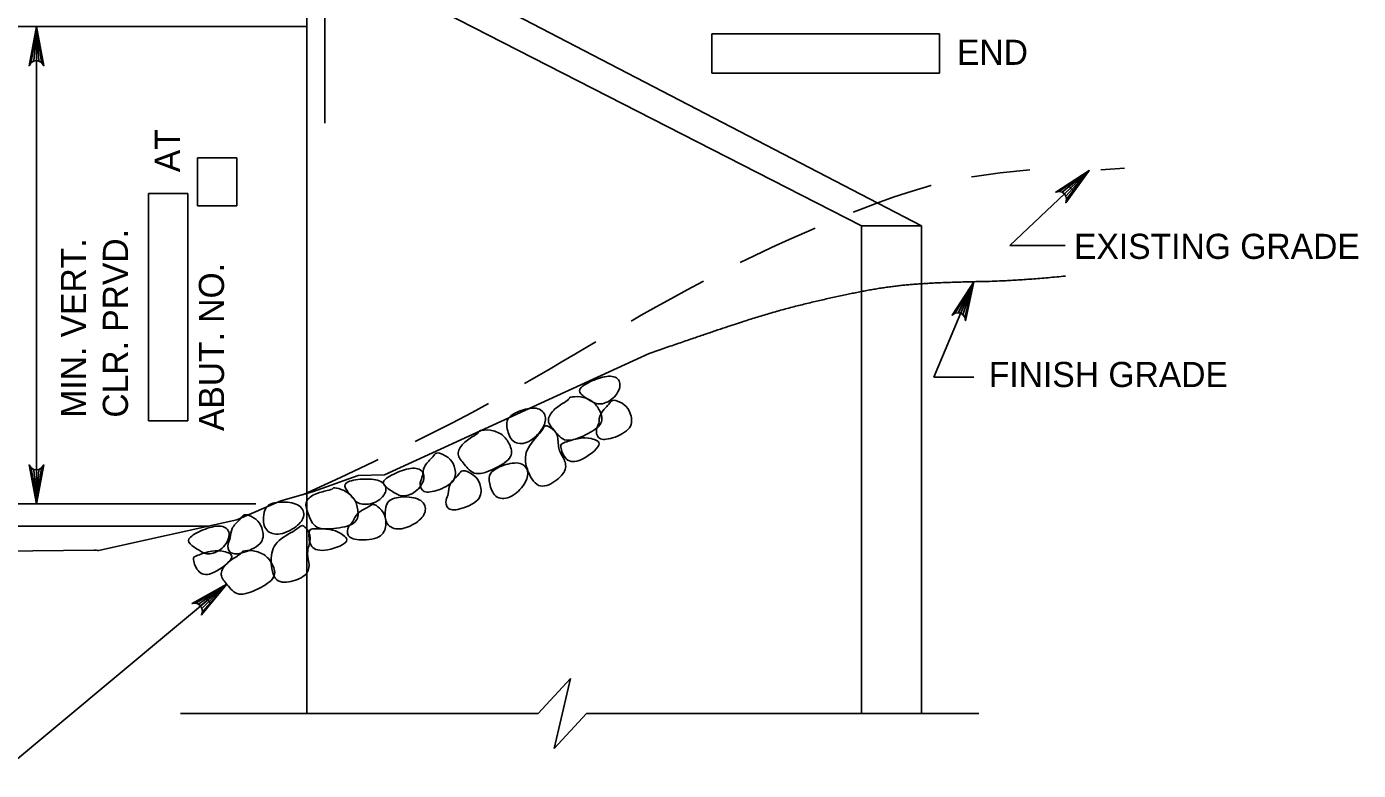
# Model space of a CAD drawing. Extents: x 638268 to 640277, y 295465 to 298435.
# Drawn here: x 638715.2 to 638874.1, y 296757 to 296845.8 of the extents above; entities that cross this region are included whole.
import ezdxf

# ---------------------------------------------------------------- set-up
doc = ezdxf.new("R2010")
doc.units = 0
for name, color, linetype in [('3', 7, 'Continuous'), ('4', 7, 'Continuous'), ('8', 7, 'Continuous')]:
    doc.layers.add(name, color=color, linetype=linetype)

msp = doc.modelspace()

# ---------------------------------------------------------------- linework, layer by layer
at = {"layer": '3'}
for p, q in [((638748.57, 296855.85), (638814.78, 296821.97)), ((638756.79, 296855.85), (638821.91, 296821.97)), ((638748.57, 296851.52), (638748.57, 296790.02)), ((638569.79, 296845.75), (638748.57, 296845.75)), ((638569.79, 296845.75), (638748.57, 296845.75)), ((638841.94, 296828.56), (638832.45, 296819.63)), ((638814.78, 296821.97), (638821.91, 296821.97)), ((638814.78, 296814.12), (638814.78, 296821.97)), ((638821.91, 296821.97), (638821.91, 296815.02)), ((638832.45, 296819.63), (638839.05, 296819.63)), ((638821.91, 296815.02), (638821.91, 296763.74)), ((638828.17, 296815.28), (638823.41, 296803.89)), ((638814.78, 296763.74), (638814.78, 296814.12)), ((638789.43, 296806.73), (638757.84, 296792.24)), ((638823.41, 296803.89), (638828.18, 296803.89)), ((638757.84, 296792.24), (638754.69, 296792.17)), ((638748.57, 296790.02), (638748.57, 296763.74)), ((638576.14, 296786.13), (638736.87, 296786.13)), ((638776.18, 296763.74), (638780.03, 296767.92)), ((638780.03, 296767.92), (638778.1, 296759.57)), ((638733.5, 296763.74), (638776.18, 296763.74)), ((638778.1, 296759.57), (638781.95, 296763.74)), ((638781.95, 296763.74), (638828.77, 296763.74))]:
    msp.add_line(p, q, dxfattribs=at)
for points in [[(638839.39, 296826.84), (638840.06, 296826.12), (638841.88, 296828.51)], [(638826.58, 296812.74), (638827.49, 296812.37), (638828.17, 296815.28)]]:
    msp.add_lwpolyline(points, close=True, dxfattribs=at)
msp.add_lwpolyline([(638634.43, 296782.51), (638657.14, 296782.51), (638723.2, 296783.23)], dxfattribs=at)
msp.add_arc((638723.2, 296771.75), 11.48, 87.4213, 90, dxfattribs=at)
for points, degree in [([(638789.43, 296806.73), (638797.21, 296809.42), (638804.35, 296811.74), (638811.5, 296813.49), (638818.25, 296814.8), (638824.6, 296815.24), (638833.14, 296815.38), (638839.1, 296815.97)], 2), ([(638781.29, 296801.9), (638781.53, 296801.64), (638782.4, 296801.09), (638783.51, 296800.44), (638785.49, 296801.38), (638786.25, 296803.31), (638785.16, 296804.22), (638783.14, 296803.78), (638780.96, 296802.63), (638781.05, 296802.16), (638781.29, 296801.9)], 3), ([(638779.88, 296801.34), (638779.83, 296801.26), (638779.49, 296800.97), (638777.91, 296800.05), (638777.11, 296798.62), (638778.12, 296797.57), (638779.32, 296795.94), (638781.9, 296796.94), (638784.12, 296798.36), (638783.57, 296799.95), (638782.78, 296801.08), (638781.18, 296801.69), (638779.83, 296801.48), (638779.94, 296801.43), (638779.88, 296801.34)], 3), ([(638783.41, 296798.4), (638783.35, 296798.1), (638783.05, 296797.73), (638783.2, 296796.51), (638784.54, 296796.34), (638787.44, 296797.59), (638787.34, 296799.35), (638786.83, 296800.45), (638785.57, 296801.15), (638784.91, 296801.18), (638784.62, 296800.57), (638783.44, 296799.54), (638783.48, 296798.7), (638783.41, 296798.4)], 3), ([(638772.65, 296799), (638772.37, 296798.63), (638772.41, 296797.79), (638773.04, 296795.97), (638774.88, 296795.83), (638776.63, 296797.45), (638777.33, 296799.09), (638776.36, 296800.43), (638774.09, 296800.02), (638772.93, 296799.37), (638772.65, 296799)], 3), ([(638769.11, 296797.36), (638769.05, 296797.28), (638768.72, 296796.99), (638767.13, 296796.07), (638766.34, 296794.64), (638767.34, 296793.59), (638768.54, 296791.96), (638771.12, 296792.96), (638773.34, 296794.38), (638772.79, 296795.97), (638772.01, 296797.1), (638770.4, 296797.71), (638769.05, 296797.5), (638769.16, 296797.44), (638769.11, 296797.36)], 3), ([(638776.97, 296798.03), (638776.84, 296797.94), (638776.72, 296797.49), (638774.46, 296795.18), (638774.71, 296792.97), (638776.11, 296790.38), (638778.31, 296791.39), (638779.72, 296792.9), (638779.25, 296794.27), (638778.5, 296795.29), (638778.64, 296797.13), (638777.56, 296798.03), (638777.11, 296798.13), (638776.97, 296798.03)], 3), ([(638779.42, 296796.12), (638779, 296795.97), (638778.7, 296795.87), (638779.41, 296793.81), (638781.13, 296793.64), (638784.25, 296796.1), (638782.41, 296796.63), (638781.22, 296796.73), (638779.84, 296796.26), (638779.42, 296796.12)], 3), ([(638762.39, 296792.11), (638762.32, 296791.81), (638762.02, 296791.44), (638762.17, 296790.22), (638763.52, 296790.05), (638766.41, 296791.3), (638766.32, 296793.05), (638765.81, 296794.15), (638764.54, 296794.86), (638763.89, 296794.89), (638763.59, 296794.28), (638762.42, 296793.25), (638762.46, 296792.41), (638762.39, 296792.11)], 3), ([(638757.9, 296790.92), (638758.14, 296790.66), (638759.01, 296790.11), (638760.12, 296789.46), (638762.1, 296790.4), (638762.86, 296792.33), (638761.77, 296793.23), (638759.75, 296792.79), (638757.57, 296791.65), (638757.66, 296791.18), (638757.9, 296790.92)], 3), ([(638765.46, 296789.99), (638765.39, 296789.69), (638765.09, 296789.32), (638765.24, 296788.1), (638766.58, 296787.93), (638769.48, 296789.18), (638769.38, 296790.93), (638768.87, 296792.03), (638767.61, 296792.74), (638766.96, 296792.77), (638766.66, 296792.16), (638765.49, 296791.13), (638765.52, 296790.29), (638765.46, 296789.99)], 3), ([(638770.55, 296792.45), (638770.27, 296792.08), (638770.31, 296791.24), (638770.94, 296789.42), (638772.78, 296789.28), (638774.53, 296790.9), (638775.22, 296792.54), (638774.26, 296793.88), (638771.98, 296793.47), (638770.83, 296792.82), (638770.55, 296792.45)], 3), ([(638753.21, 296790.66), (638753.35, 296790.34), (638753.99, 296789.54), (638754.83, 296788.57), (638757.01, 296788.81), (638758.35, 296790.39), (638757.62, 296791.6), (638755.56, 296791.84), (638753.13, 296791.47), (638753.06, 296790.99), (638753.21, 296790.66)], 3), ([(638751.69, 296790.59), (638751.61, 296790.53), (638751.2, 296790.37), (638749.4, 296790.02), (638748.19, 296788.92), (638748.8, 296787.6), (638749.4, 296785.67), (638752.17, 296785.78), (638754.73, 296786.4), (638754.73, 296788.09), (638754.35, 296789.41), (638753.03, 296790.5), (638751.69, 296790.74), (638751.77, 296790.66), (638751.69, 296790.59)], 3), ([(638758.52, 296789.22), (638758.14, 296788.96), (638757.9, 296788.15), (638757.9, 296786.22), (638759.6, 296785.5), (638761.78, 296786.46), (638762.97, 296787.78), (638762.49, 296789.36), (638760.21, 296789.72), (638758.91, 296789.48), (638758.52, 296789.22)], 3), ([(638744.01, 296788.61), (638743.62, 296788.35), (638743.39, 296787.55), (638743.39, 296785.62), (638745.09, 296784.89), (638747.26, 296785.86), (638748.46, 296787.18), (638747.97, 296788.75), (638745.69, 296789.11), (638744.39, 296788.87), (638744.01, 296788.61)], 3), ([(638754.08, 296786.67), (638753.92, 296786.4), (638753.51, 296786.15), (638753.26, 296784.95), (638754.47, 296784.35), (638757.62, 296784.59), (638758.1, 296786.28), (638757.97, 296787.49), (638757.01, 296788.57), (638756.4, 296788.81), (638755.92, 296788.33), (638754.47, 296787.73), (638754.24, 296786.93), (638754.08, 296786.67)], 3), ([(638739.45, 296784.74), (638739.39, 296784.43), (638739.09, 296784.07), (638739.24, 296782.84), (638740.58, 296782.68), (638743.47, 296783.93), (638743.38, 296785.68), (638742.87, 296786.78), (638741.61, 296787.49), (638740.95, 296787.52), (638740.66, 296786.91), (638739.48, 296785.88), (638739.52, 296785.04), (638739.45, 296784.74)], 3), ([(638734.65, 296784.01), (638734.89, 296783.75), (638735.76, 296783.2), (638736.87, 296782.55), (638738.85, 296783.49), (638739.61, 296785.42), (638738.52, 296786.32), (638736.5, 296785.89), (638734.32, 296784.74), (638734.41, 296784.27), (638734.65, 296784.01)], 3), ([(638747.95, 296786.17), (638747.79, 296786.13), (638747.54, 296785.73), (638744.65, 296784.28), (638744.17, 296782.1), (638744.65, 296779.21), (638747.06, 296779.45), (638748.88, 296780.42), (638748.88, 296781.86), (638748.5, 296783.07), (638749.24, 296784.76), (638748.5, 296785.97), (638748.11, 296786.21), (638747.95, 296786.17)], 3), ([(638749.56, 296785.8), (638749.12, 296785.8), (638748.8, 296785.8), (638748.8, 296783.63), (638750.37, 296782.9), (638754.12, 296784.22), (638752.55, 296785.32), (638751.46, 296785.8), (638750, 296785.8), (638749.56, 296785.8)], 3), ([(638735.59, 296782.64), (638735.18, 296782.5), (638734.87, 296782.39), (638735.58, 296780.34), (638737.3, 296780.16), (638740.42, 296782.63), (638738.58, 296783.15), (638737.39, 296783.26), (638736.01, 296782.79), (638735.59, 296782.64)], 3), ([(638740.83, 296782.96), (638740.77, 296782.88), (638740.44, 296782.6), (638738.85, 296781.68), (638738.06, 296780.25), (638739.06, 296779.2), (638740.27, 296777.57), (638742.84, 296778.57), (638745.07, 296779.98), (638744.52, 296781.58), (638743.73, 296782.7), (638742.12, 296783.31), (638740.78, 296783.1), (638740.89, 296783.05), (638740.83, 296782.96)], 3)]:
    msp.add_open_spline(points, degree=degree, dxfattribs=at)
at = {"layer": '4'}
for p, q in [((638750.73, 296886.72), (638750.73, 296834.24)), ((638716.31, 296788.77), (638716.31, 296845.75)), ((638824.06, 296844.9), (638796.91, 296844.9)), ((638796.91, 296840.2), (638796.91, 296844.9)), ((638824.06, 296840.2), (638824.06, 296844.9)), ((638796.91, 296840.2), (638824.06, 296840.2)), ((638735.52, 296830.09), (638735.52, 296824.34)), ((638740.23, 296830.09), (638735.52, 296830.09)), ((638740.23, 296824.34), (638740.23, 296830.09)), ((638729.68, 296825.83), (638729.68, 296798.68)), ((638734.39, 296825.83), (638729.68, 296825.83)), ((638734.39, 296798.68), (638734.39, 296825.83)), ((638740.23, 296824.34), (638735.52, 296824.34)), ((638734.39, 296798.68), (638729.68, 296798.68)), ((638711.69, 296788.77), (638742.51, 296788.77)), ((638739.03, 296779.18), (638712.39, 296756.95))]:
    msp.add_line(p, q, dxfattribs=at)
for points in [[(638716.31, 296845.75), (638717.19, 296841.09), (638716.94, 296841.45), (638716.62, 296841.64), (638716.31, 296841.69), (638716, 296841.64), (638715.69, 296841.45), (638715.44, 296841.09), (638716.31, 296845.75), (638715.69, 296841.45), (638716, 296841.64), (638716.31, 296845.75), (638716.31, 296841.69), (638716.62, 296841.64), (638716.31, 296845.75), (638716.94, 296841.45)], [(638841.94, 296828.56), (638839.14, 296824.73), (638839.23, 296825.16), (638839.15, 296825.51), (638838.98, 296825.78), (638838.72, 296825.97), (638838.37, 296826.07), (638837.94, 296826), (638841.94, 296828.56), (638838.37, 296826.07), (638838.72, 296825.97), (638841.94, 296828.56), (638838.98, 296825.78), (638839.15, 296825.51), (638841.94, 296828.56), (638839.23, 296825.16)], [(638828.17, 296815.28), (638827.18, 296810.64), (638827.09, 296811.07), (638826.87, 296811.36), (638826.61, 296811.53), (638826.3, 296811.6), (638825.94, 296811.55), (638825.57, 296811.32), (638828.17, 296815.28), (638825.94, 296811.55), (638826.3, 296811.6), (638828.17, 296815.28), (638826.61, 296811.53), (638826.87, 296811.36), (638828.17, 296815.28), (638827.09, 296811.07)], [(638716.31, 296788.77), (638715.44, 296793.43), (638715.69, 296793.08), (638716, 296792.89), (638716.31, 296792.84), (638716.62, 296792.89), (638716.94, 296793.08), (638717.19, 296793.43), (638716.31, 296788.77), (638716.94, 296793.08), (638716.62, 296792.89), (638716.31, 296788.77), (638716.31, 296792.84), (638716, 296792.89), (638716.31, 296788.77), (638715.69, 296793.08)], [(638723.72, 296783.22), (638740.24, 296786.88), (638745.49, 296789.13), (638749.26, 296790.22), (638754.69, 296792.17)], [(638739.03, 296779.18), (638736.01, 296775.52), (638736.13, 296775.94), (638736.07, 296776.3), (638735.91, 296776.58), (638735.67, 296776.78), (638735.33, 296776.9), (638734.89, 296776.87), (638739.03, 296779.18), (638735.33, 296776.9), (638735.67, 296776.78), (638739.03, 296779.18), (638735.91, 296776.58), (638736.07, 296776.3), (638739.03, 296779.18), (638736.13, 296775.94)]]:
    msp.add_lwpolyline(points, dxfattribs=at)
for points in [[(638715.82, 296791.73), (638716.81, 296791.73), (638716.31, 296788.77)], [(638736.45, 296777.67), (638737.08, 296776.91), (638739.03, 296779.18)]]:
    msp.add_lwpolyline(points, close=True, dxfattribs=at)
at = {"layer": '8'}
for p, q in [((638827.9, 296827.8), (638828.24, 296827.86)), ((638828.24, 296827.86), (638831.33, 296828.3)), ((638831.33, 296828.3), (638834.86, 296828.65)), ((638843.32, 296828.65), (638846.15, 296828.84)), ((638818.68, 296825.42), (638820.8, 296826.12)), ((638820.8, 296826.12), (638823.05, 296826.77)), ((638823.05, 296826.77), (638823.09, 296826.78)), ((638814.54, 296823.88), (638816.61, 296824.67)), ((638816.61, 296824.67), (638818.68, 296825.42)), ((638813.79, 296823.58), (638814.54, 296823.88)), ((638808.24, 296821.27), (638809.24, 296821.7)), ((638804.04, 296819.38), (638806.13, 296820.34)), ((638806.13, 296820.34), (638808.24, 296821.27)), ((638800.3, 296817.58), (638801.97, 296818.4)), ((638801.97, 296818.4), (638804.04, 296819.38)), ((638793.98, 296814.32), (638795.92, 296815.35)), ((638792.09, 296813.3), (638793.98, 296814.32)), ((638788.49, 296811.29), (638790.26, 296812.28)), ((638790.26, 296812.28), (638792.09, 296813.3)), ((638787.3, 296810.6), (638788.49, 296811.29)), ((638780.63, 296806.69), (638782.11, 296807.57)), ((638782.11, 296807.57), (638783.05, 296808.12)), ((638777.61, 296804.91), (638779.14, 296805.8)), ((638779.14, 296805.8), (638780.63, 296806.69)), ((638774.55, 296803.15), (638776.01, 296803.98)), ((638776.01, 296803.98), (638777.61, 296804.91)), ((638768.31, 296799.7), (638770.25, 296800.75)), ((638765.87, 296798.42), (638768.31, 296799.7)), ((638763.12, 296797.02), (638765.87, 296798.42)), ((638761.52, 296796.22), (638763.12, 296797.02)), ((638752.6, 296791.94), (638756.54, 296793.79)), ((638756.54, 296793.79), (638757.1, 296794.06)), ((638748.17, 296789.9), (638752.6, 296791.94))]:
    msp.add_line(p, q, dxfattribs=at)

# ---------------------------------------------------------------- texts
at = {"layer": '4'}
for s, p in [('END', (638826.16, 296841.19)), ('EXISTING GRADE', (638840.12, 296818.02)), ('FINISH GRADE', (638829.96, 296802.72))]:
    msp.add_text(s, height=3, dxfattribs=at).set_placement(p)
for s, p in [('AT', (638733.44, 296828.37)), ('MIN. VERT.', (638722.24, 296799.07)), ('CLR. PRVD.', (638727.24, 296799.07)), ('ABUT. NO. ', (638738.7, 296797.47))]:
    msp.add_text(s, height=3, rotation=90, dxfattribs=at).set_placement(p)

doc.saveas('drawing.dxf')
